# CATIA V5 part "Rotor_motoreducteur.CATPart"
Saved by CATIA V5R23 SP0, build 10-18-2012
Part number: Rotor_motoreducteur
Bounding box of the stored display mesh (mm): x -5 to 5, y -5 to 5, z 0 to 57.75
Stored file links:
  P:\CORRECTION CAO\Rotor_motoreducteur.CATPart
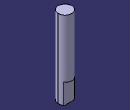
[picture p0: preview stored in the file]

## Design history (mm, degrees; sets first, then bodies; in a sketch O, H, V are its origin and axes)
Body1 (main body)
  Sketch1 on xy-plane, origin (0, 0, 0), H (1, 0, 0), V (0, 1, 0)
    circle A1 centre (0, 0) radius 5
    radius A1 = 5
  Pad1: profile Sketch1, direction (0, 0, 1), length 57.75
  Sketch2 on xy-plane, origin (0, 0, 0), H (1, 0, 0), V (0, 1, 0)
    line L1 (-5, 5) -> (5, 5)
    line L2 (5, 5) -> (5, 3)
    line L3 (5, 3) -> (-5, 3)
    line L4 (-5, 3) -> (-5, 5)
    reference projected circle E1 centre (0, 0) radius 5 from edge [face of Pad1 from Sketch1.A1 | end face of Pad1]
    reference projected circle E4 centre (0, 0) radius 5 from edge [face of Pad1 from Sketch1.A1 | end face of Pad1]
    reference projected circle E7 centre (0, 0) radius 5 from edge [face of Pad1 from Sketch1.A1 | end face of Pad1]
    reference projected circle E10 centre (0, 0) radius 5 from edge [face of Pad1 from Sketch1.A1 | end face of Pad1]
    distance E1 L3 = 2
    horizontal: L1 H, L3 H
    vertical: L2 V, L4 V
    tangency: L1 E4, L4 E7, L2 E10
  Pocket1: profile Sketch2, direction (0, 0, 1), length 15
  Chamfer1: length 0.5, angle 45, on edge [start face of Pad1 | face of Pad1 from Sketch1.A1]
